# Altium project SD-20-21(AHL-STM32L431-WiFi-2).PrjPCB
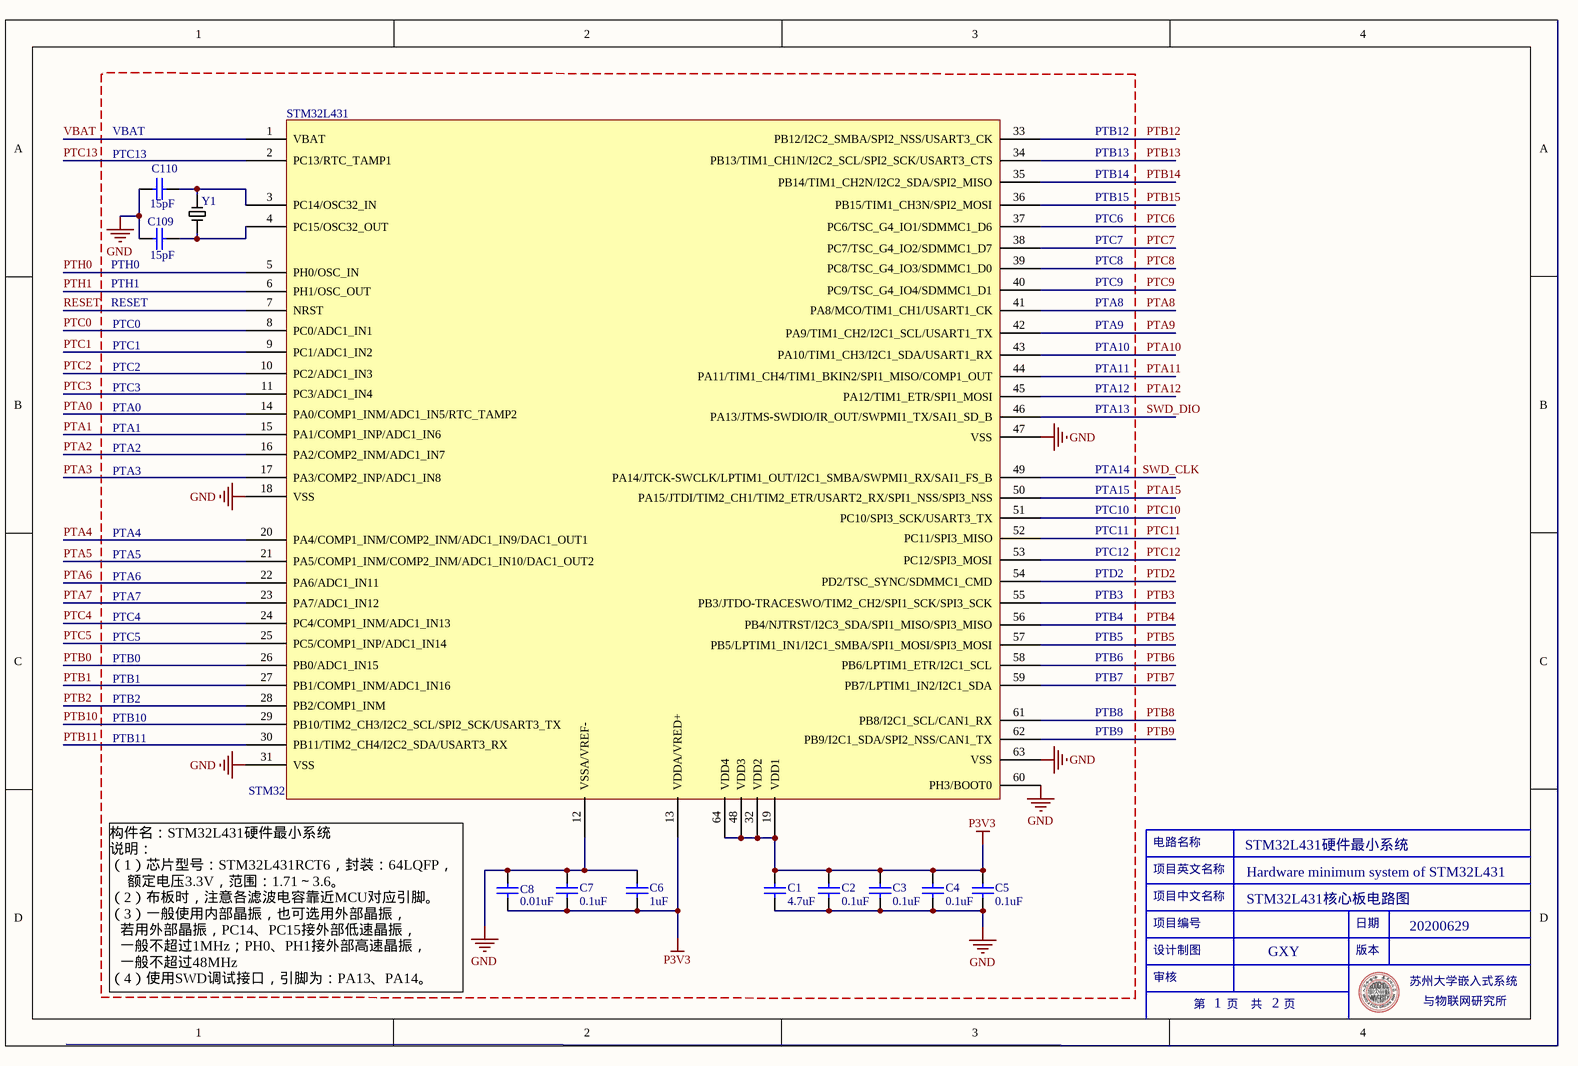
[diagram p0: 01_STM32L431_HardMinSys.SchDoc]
4 sheets, 60 parts. Net scope: global (net labels, ports and power ports of the same name join across sheets).
Board file: SD-20-21(AHL-STM32L431-WiFi-3).PcbDoc
Sheets:
  01_STM32L431_HardMinSys.SchDoc
  02_interface.SchDoc
  03_Wi-Fi-ESP8266.SchDoc
  Tsensor.SchDoc

## Sheet 01_STM32L431_HardMinSys.SchDoc
size A4; PageSetup: Record=PageOptions¦CenterHorizontal=True¦CenterVertical=True¦PrintScale=0.97¦XCorrection=1.00¦YCorrection=1.00¦PrintKind=1¦BorderSize=5000000¦LeftOffset=0¦BottomOffset=0¦Orientation=2¦PaperLength=1000¦PaperWidth=1000¦Scale=100¦PaperSource=15¦PrintQuality=1200¦MediaType=1¦DitherType=10¦PaperKind=A4¦PrintScaleMode=1

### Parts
C1  value 4.7uF  [0402]  (hidden comment: Cap)
C2  value 0.1uF  [0402]  (hidden comment: Cap)
C3  value 0.1uF  [0402]  (hidden comment: Cap)
C4  value 0.1uF  [0402]  (hidden comment: Cap)
C5  value 0.1uF  [0402]  (hidden comment: Cap)
C6  value 1uF  [0402]  (hidden comment: Cap)
C7  value 0.1uF  [0402]  (hidden comment: Cap)
C8  value 0.01uF  [0402]  (hidden comment: Cap)
C109  value 15pF  [0402]  (hidden comment: Cap)
C110  value 15pF  [0402]  (hidden comment: Cap)
STM32L431  STM32  [LQFP64]
Y1  resonnator  [osc]  (value not drawn)

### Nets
GND: C1.1 C2.1 C3.1 C4.1 C5.1 C6.1 C7.1 C8.1 C109.1 C110.1 STM32L431.12(VSSA/VREF-) STM32L431.18(VSS) STM32L431.31(VSS) STM32L431.47(VSS) STM32L431.60(PH3/BOOT0) STM32L431.63(VSS)
P3V3: C1.2 C2.2 C3.2 C4.2 C5.2 C6.2 C7.2 C8.2 STM32L431.13(VDDA/VRED+) STM32L431.19(VDD1) STM32L431.32(VDD2) STM32L431.48(VDD3) STM32L431.64(VDD4)
PTA0: STM32L431.14(PA0/COMP1_INM/ADC1_IN5/RTC_TAMP2)
PTA1: STM32L431.15(PA1/COMP1_INP/ADC1_IN6)
PTA2: STM32L431.16(PA2/COMP2_INM/ADC1_IN7)
PTA3: STM32L431.17(PA3/COMP2_INP/ADC1_IN8)
PTA4: STM32L431.20(PA4/COMP1_INM/COMP2_INM/ADC1_IN9/DAC1_OUT1)
PTA5: STM32L431.21(PA5/COMP1_INM/COMP2_INM/ADC1_IN10/DAC1_OUT2)
PTA6: STM32L431.22(PA6/ADC1_IN11)
PTA7: STM32L431.23(PA7/ADC1_IN12)
PTA8: STM32L431.41(PA8/MCO/TIM1_CH1/USART1_CK)
PTA9: STM32L431.42(PA9/TIM1_CH2/I2C1_SCL/USART1_TX)
PTA10: STM32L431.43(PA10/TIM1_CH3/I2C1_SDA/USART1_RX)
PTA11: STM32L431.44(PA11/TIM1_CH4/TIM1_BKIN2/SPI1_MISO/COMP1_OUT)
PTA12: STM32L431.45(PA12/TIM1_ETR/SPI1_MOSI)
PTA15: STM32L431.50(PA15/JTDI/TIM2_CH1/TIM2_ETR/USART2_RX/SPI1_NSS/SPI3_NSS)
PTB0: STM32L431.26(PB0/ADC1_IN15)
PTB1: STM32L431.27(PB1/COMP1_INM/ADC1_IN16)
PTB2: STM32L431.28(PB2/COMP1_INM)
PTB3: STM32L431.55(PB3/JTDO-TRACESWO/TIM2_CH2/SPI1_SCK/SPI3_SCK)
PTB4: STM32L431.56(PB4/NJTRST/I2C3_SDA/SPI1_MISO/SPI3_MISO)
PTB5: STM32L431.57(PB5/LPTIM1_IN1/I2C1_SMBA/SPI1_MOSI/SPI3_MOSI)
PTB6: STM32L431.58(PB6/LPTIM1_ETR/I2C1_SCL)
PTB7: STM32L431.59(PB7/LPTIM1_IN2/I2C1_SDA)
PTB8: STM32L431.61(PB8/I2C1_SCL/CAN1_RX)
PTB9: STM32L431.62(PB9/I2C1_SDA/SPI2_NSS/CAN1_TX)
PTB10: STM32L431.29(PB10/TIM2_CH3/I2C2_SCL/SPI2_SCK/USART3_TX)
PTB11: STM32L431.30(PB11/TIM2_CH4/I2C2_SDA/USART3_RX)
PTB12: STM32L431.33(PB12/I2C2_SMBA/SPI2_NSS/USART3_CK)
PTB13: STM32L431.34(PB13/TIM1_CH1N/I2C2_SCL/SPI2_SCK/USART3_CTS)
PTB14: STM32L431.35(PB14/TIM1_CH2N/I2C2_SDA/SPI2_MISO)
PTB15: STM32L431.36(PB15/TIM1_CH3N/SPI2_MOSI)
PTC0: STM32L431.8(PC0/ADC1_IN1)
PTC1: STM32L431.9(PC1/ADC1_IN2)
PTC2: STM32L431.10(PC2/ADC1_IN3)
PTC3: STM32L431.11(PC3/ADC1_IN4)
PTC4: STM32L431.24(PC4/COMP1_INM/ADC1_IN13)
PTC5: STM32L431.25(PC5/COMP1_INP/ADC1_IN14)
PTC6: STM32L431.37(PC6/TSC_G4_IO1/SDMMC1_D6)
PTC7: STM32L431.38(PC7/TSC_G4_IO2/SDMMC1_D7)
PTC8: STM32L431.39(PC8/TSC_G4_IO3/SDMMC1_D0)
PTC9: STM32L431.40(PC9/TSC_G4_IO4/SDMMC1_D1)
PTC10: STM32L431.51(PC10/SPI3_SCK/USART3_TX)
PTC11: STM32L431.52(PC11/SPI3_MISO)
PTC12: STM32L431.53(PC12/SPI3_MOSI)
PTC13: STM32L431.2(PC13/RTC_TAMP1)
PTD2: STM32L431.54(PD2/TSC_SYNC/SDMMC1_CMD)
PTH0: STM32L431.5(PH0/OSC_IN)
PTH1: STM32L431.6(PH1/OSC_OUT)
RESET: STM32L431.7(NRST)
SWD_CLK: STM32L431.49(PA14/JTCK-SWCLK/LPTIM1_OUT/I2C1_SMBA/SWPMI1_RX/SAI1_FS_B)
SWD_DIO: STM32L431.46(PA13/JTMS-SWDIO/IR_OUT/SWPMI1_TX/SAI1_SD_B)
VBAT: STM32L431.1(VBAT)
NetC109_2: C109.2 STM32L431.4(PC15/OSC32_OUT) Y1.2
NetC110_2: C110.2 STM32L431.3(PC14/OSC32_IN) Y1.1

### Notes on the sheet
- (near C110) PTC13
- (near C110) VBAT
- PTB12
- PTB13
- PTB14
- PTB15
- PTC6
- PTC7
- PTC8
- RESET
- (near C109) PTH1
- (near C109) PTH0
- PTC0
- PTC9
- PTA8
- PTA9
- PTC1
- PTC2
- PTC3
- PTA10
- PTA11
- PTA12
- PTA0
- PTA1
- PTA2
- PTA13
- PTA3
- PTC10
- PTC11
- PTA14
- PTA15
- PTA4
- PTA5
- PTA6
- PTA7
- PTC12
- PTB3
- PTD2
- PTC4
- PTC5
- PTB0
- PTB4
- PTB5
- PTB6
- PTB1
- PTB2
- PTB10
- PTB7
- PTB8
- PTB9
- PTB11
- STM32L431硬件最小系统
- STM32L431核心板电路图
- Hardware minimum system of STM32L431
- 20200629
- (near STM32L431) 构件名：STM32L431硬件最小系统
  说明：
  （1）芯片型号：STM32L431RCT6，封装：64LQFP，
  额定电压3.3V，范围：1.71～3.6。
  （2）布板时，注意各滤波电容靠近MCU对应引脚。
  （3）一般使用内部晶振，也可选用外部晶振，
  若用外部晶振，PC14、PC15接外部低速晶振，
  一般不超过1MHz；PH0、PH1接外部高速晶振，
  一般不超过48MHz
  （4）使用SWD调试接口，引脚为：PA13、PA14。
- GXY
- 1
- 2

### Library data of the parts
C1-C8 C109 C110 = Cap: Capacitor

## Sheet 02_interface.SchDoc
size A4; PageSetup: Record=PageOptions¦CenterHorizontal=True¦CenterVertical=True¦PrintScale=1.00¦XCorrection=1.00¦YCorrection=1.00¦PrintKind=1¦BorderSize=5000000¦LeftOffset=0¦BottomOffset=0¦Orientation=2¦PaperLength=1000¦PaperWidth=1000¦Scale=100¦PaperSource=15¦PrintQuality=1200¦MediaType=1¦DitherType=10¦PaperKind=A4¦PrintScaleMode=1
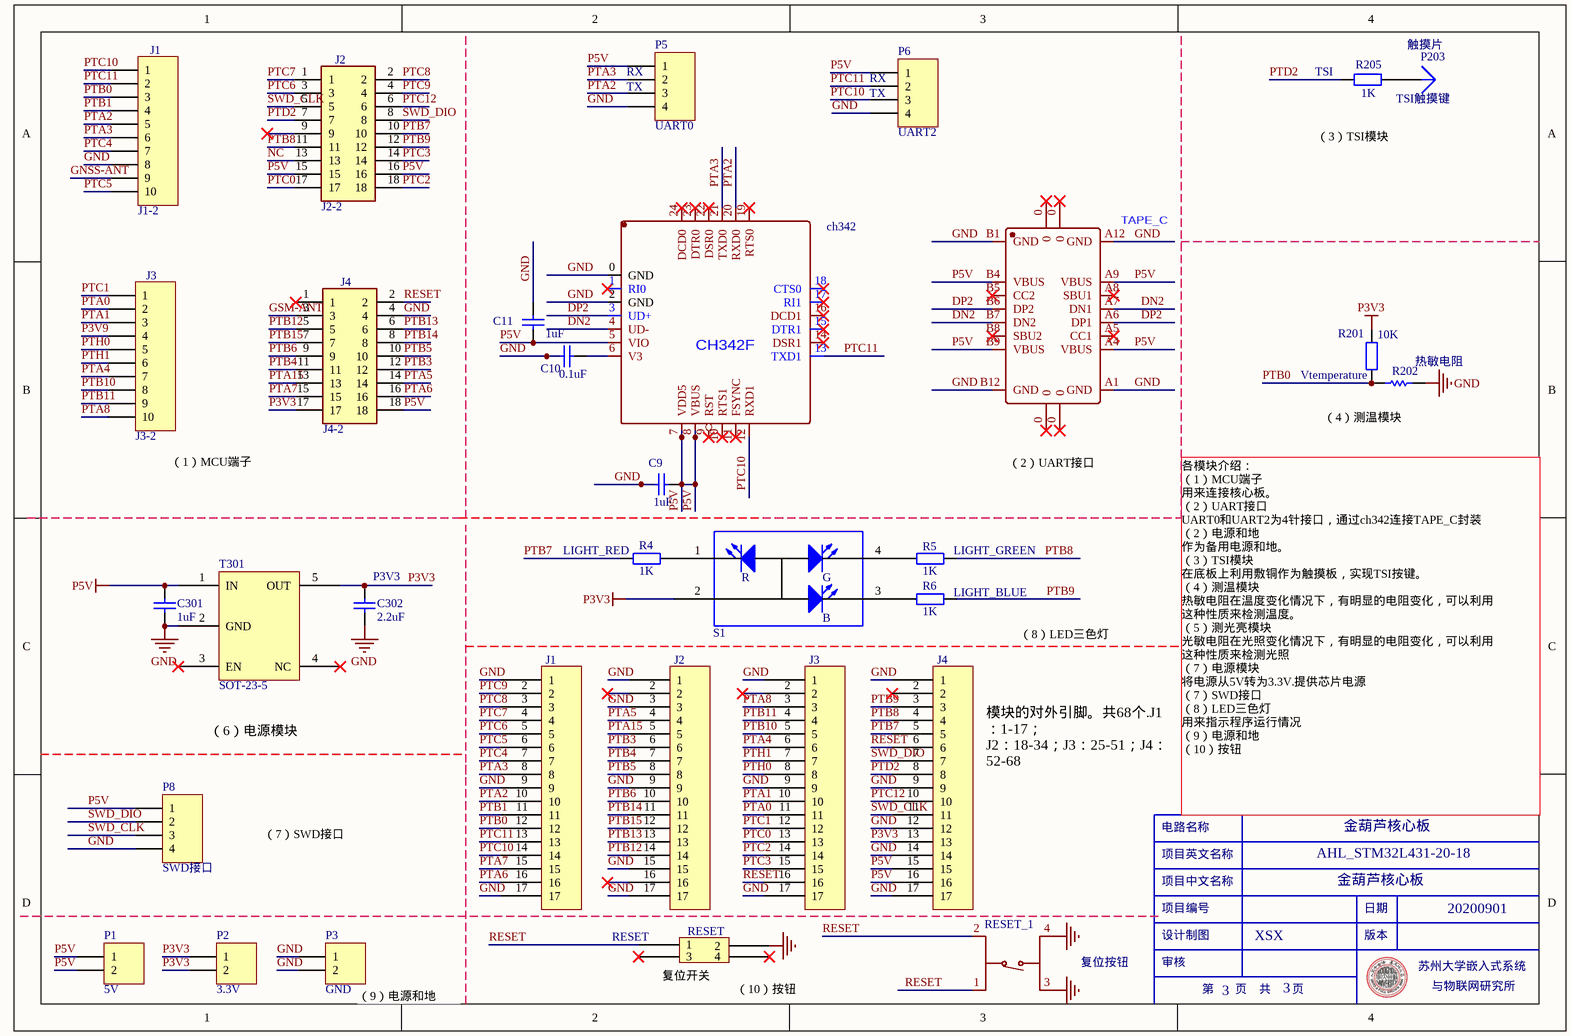
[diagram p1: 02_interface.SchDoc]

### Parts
(Parts that share a designator on the sheet are numbered #1, #2 ... from top to bottom, then left to right.)
C9  value 1uF  [0603]  (hidden comment: Cap)
C10  value 0.1uF  [0603]  (hidden comment: Cap)
C11  value 1uF  [0603]  (hidden comment: Cap)
C301  value 1uF  [0402]  (hidden comment: 0402)
C302  value 2.2uF  [0402]  (hidden comment: 0402)
ch342  ch342  [ch342]  (value not drawn)
J1#1  J1-2  [HDR1X10]
J1#2  HEADERX17(new)  [HEADERX17(new)]  (value not drawn)
J2#1  J2-2  [IDC2X9]
J2#2  HEADERX17(new)  [HEADERX17(new)]  (value not drawn)
J3#1  J3-2  [HDR1X10]
J3#2  HEADERX17(new)  [HEADERX17(new)]  (value not drawn)
J4#1  J4-2  [IDC2X9]
J4#2  HEADERX17(new)  [HEADERX17(new)]  (value not drawn)
P1  5V  [HDR1X2]
P2  3.3V  [HDR1X2]
P3  GND  [HDR1X2]
P5  UART0  [HDR1X4]
P6  UART2  [HDR1X4]
P8  SWD接口  [HDR1X4]
P203  TSI触摸键  [TSI]
R4  value 1K  [0603]  (hidden comment: Res2)
R5  value 1K  [0603]  (hidden comment: Res2)
R6  value 1K  [0603]  (hidden comment: Res2)
R201  value 10K  [0603]  (hidden comment: Res2)
R202  热敏电阻  [0603]
R205  value 1K  [0603]  (hidden comment: Res2)
RESET  RESET  [RESET_KEY]  (value not drawn)
RESET_1  复位按钮  [复位按钮]
S1  Single-Pole, Single-Throw Switch  [LED3]  (value not drawn)
T301  SOT-23-5  [SOT-23-5]
TAPE_C  TYPE-C-31-M-12  [TYPE_C]  (value not drawn)

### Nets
GND: C9.2 C10.1 C11.2 C301.1 C302.1 ch342.0(GND) ch342.2(GND) J1#1.8 J1#2.1 J1#2.9 J1#2.17 J2#2.1 J2#2.3 J2#2.9 J2#2.15 J2#2.17 J3#2.1 J3#2.9 J3#2.17 J4#1.4 J4#2.1 J4#2.9 J4#2.12 J4#2.14 J4#2.17 P3.1 P3.2 P5.4 P6.4 P8.4 R202.1 RESET.2 RESET_1.3(C) RESET_1.4(D) T301.2(GND) TAPE_C.A1(GND) TAPE_C.A12(GND) TAPE_C.B1(GND) TAPE_C.B12(GND)
P3V3: C302.2 J4#1.17 J4#2.13 P2.1 P2.2 R201.2 S1.2 T301.5(OUT)
P5V: C9.1 C11.1 C301.2 ch342.5(VIO) ch342.7(VDD5) ch342.8(VBUS) J2#1.15 J2#1.16 J4#1.18 J4#2.15 J4#2.16 P1.1 P1.2 P5.1 P6.1 P8.1 T301.1(IN) TAPE_C.A4(VBUS) TAPE_C.A9(VBUS) TAPE_C.B4(VBUS) TAPE_C.B9(VBUS)
DN2: ch342.4(UD-) TAPE_C.A7(DN1) TAPE_C.B7(DN2)
DP2: ch342.3(UD+) TAPE_C.A6(DP1) TAPE_C.B6(DP2)
GNSS-ANT: J1#1.9
GSM-ANT: J4#1.3
NC: J2#1.13
P3V9: J3#1.4
PTA0: J3#1.2 J3#2.11
PTA1: J3#1.3 J3#2.10
PTA2: ch342.20(RXD0) J1#1.5 J1#2.10 P5.3
PTA3: ch342.21(TXD0) J1#1.6 J1#2.8 P5.2
PTA4: J3#1.7 J3#2.6
PTA5: J2#2.4 J4#1.14
PTA6: J1#2.16 J4#1.16
PTA7: J1#2.15 J4#1.15
PTA8: J3#1.10 J3#2.3
PTA15: J2#2.5 J4#1.13
PTB0: J1#1.3 J1#2.12 R201.1 R202.2
PTB1: J1#1.4 J1#2.11
PTB3: J2#2.6 J4#1.12
PTB4: J2#2.7 J4#1.11
PTB5: J2#2.8 J4#1.10
PTB6: J2#2.10 J4#1.9
PTB7: J2#1.10 J4#2.5 R4.1
PTB8: J2#1.11 J4#2.4 R5.2
PTB9: J2#1.12 J4#2.3 R6.2
PTB10: J3#1.8 J3#2.5
PTB11: J3#1.9 J3#2.4
PTB12: J2#2.14 J4#1.5
PTB13: J2#2.13 J4#1.6
PTB14: J2#2.11 J4#1.8
PTB15: J2#2.12 J4#1.7
PTC0: J2#1.17 J3#2.13
PTC1: J3#1.1 J3#2.12
PTC2: J2#1.18 J3#2.14
PTC3: J2#1.14 J3#2.15
PTC4: J1#1.7 J1#2.7
PTC5: J1#1.10 J1#2.6
PTC6: J1#2.5 J2#1.3
PTC7: J1#2.4 J2#1.1
PTC8: J1#2.3 J2#1.2
PTC9: J1#2.2 J2#1.4
PTC10: ch342.12(RXD1) J1#1.1 J1#2.14 P6.3
PTC11: ch342.13(TXD1) J1#1.2 J1#2.13 P6.2
PTC12: J2#1.6 J4#2.10
PTD2: J2#1.7 J4#2.8 R205.1
PTH0: J3#1.5 J3#2.8
PTH1: J3#1.6 J3#2.7
RESET: J3#2.16 J4#1.2 J4#2.6 RESET.1 RESET_1.1(A) RESET_1.2(B)
SWD_CLK: J2#1.5 J4#2.11 P8.3
SWD_DIO: J2#1.8 J4#2.7 P8.2
NetC10_2: C10.2 ch342.6(V3)
NetP203_1: P203.1 R205.2
NetR4_2: R4.2 S1.1
NetR5_1: R5.1 S1.4
NetR6_1: R6.1 S1.3

Not connected (* = marked no-connect by the designer): ch342 1(RI0)* 9(RST)* 10(RTS1)* 11(FSYNC)* 14(DSR1)* 15(DTR1)* 16(DCD1)* 17(RI1)* 18(CTS0)* 19(RTS0)* 22(DSR0)* 23(DTR0)* 24(DCD0)*; J2#1 9*; J2#2 2* 16*; J3#2 2*; J4#1 1*; J4#2 2*; RESET 3* 4*; T301 3(EN)* 4(NC)*; TAPE_C 0* A5(CC1)* A8(SBU1)* B5(CC2)* B8(SBU2)*

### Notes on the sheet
- (near P5) TX
- (near P5) RX
- (near P6) TX
- (near P6) RX
- (near R205) TSI
- 触摸片
- （3）TSI模块
- (near R201) Vtemperature
- （4）测温模块
- （1）MCU端子
- (near TAPE_C) （2）UART接口
- (near C302) P3V3
- (near R4) LIGHT_RED
- (near R5) LIGHT_GREEN
- (near R6) LIGHT_BLUE
- （8）LED三色灯
- （6）电源模块
- (near J4#2) 模块的对外引脚。共68个.J1：1-17；
  J2：18-34；J3：25-51；J4：52-68
- （7）SWD接口
- 各模块介绍：
  （1）MCU端子
  用来连接核心板。
  （2）UART接口
  UART0和UART2为4针接口，通过ch342连接TAPE_C封装
  （2）电源和地
  作为备用电源和地。
  （3）TSI模块
  在底板上利用敷铜作为触摸板，实现TSI按键。
  （4）测温模块
  热敏电阻在温度变化情况下，有明显的电阻变化，可以利用
  这种性质来检测温度。
  （5）测光亮模块
  光敏电阻在光照变化情况下，有明显的电阻变化，可以利用
  这种性质来检测光照
  （7）电源模块
  将电源从5V转为3.3V.提供芯片电源
  （7）SWD接口
  （8）LED三色灯
  用来指示程序运行情况
  （9）电源和地
  （10）按钮
- 金葫芦核心板
- AHL_STM32L431-20-18
- 20200901
- RESET
- (near RESET) 复位开关
- XSX
- (near P3) （9）电源和地
- (near RESET) （10）按钮
- 3

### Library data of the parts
C9-C11 = Cap: Capacitor
C301 C302 = Cap: Capacitor; Manufacturer: Generic Components; Class: Passive
J1#1 J3#1 = Header 10: Header, 10-Pin
J2#1 J4#1 = CON2X9
P1-P3 = Header 2: Header, 2-Pin
P5 P6 P8 = Header 4: Header, 4-Pin
P203 = Plug
R4-R6 R201 R205 = Res2: Resistor
R202 = Res1: Resistor; Value: 1K
S1 = LED_3
T301 = SOT-23-5: TPS70933

## Sheet 03_Wi-Fi-ESP8266.SchDoc
size A4; PageSetup: Record=PageOptions¦CenterHorizontal=True¦CenterVertical=True¦PrintScale=1.00¦XCorrection=1.00¦YCorrection=1.00¦PrintKind=1¦BorderSize=5000000¦LeftOffset=0¦BottomOffset=0¦Orientation=2¦PaperLength=1000¦PaperWidth=1000¦Scale=100¦PaperSource=15¦PrintQuality=1200¦MediaType=1¦DitherType=10¦PaperKind=A4¦PrintScaleMode=1
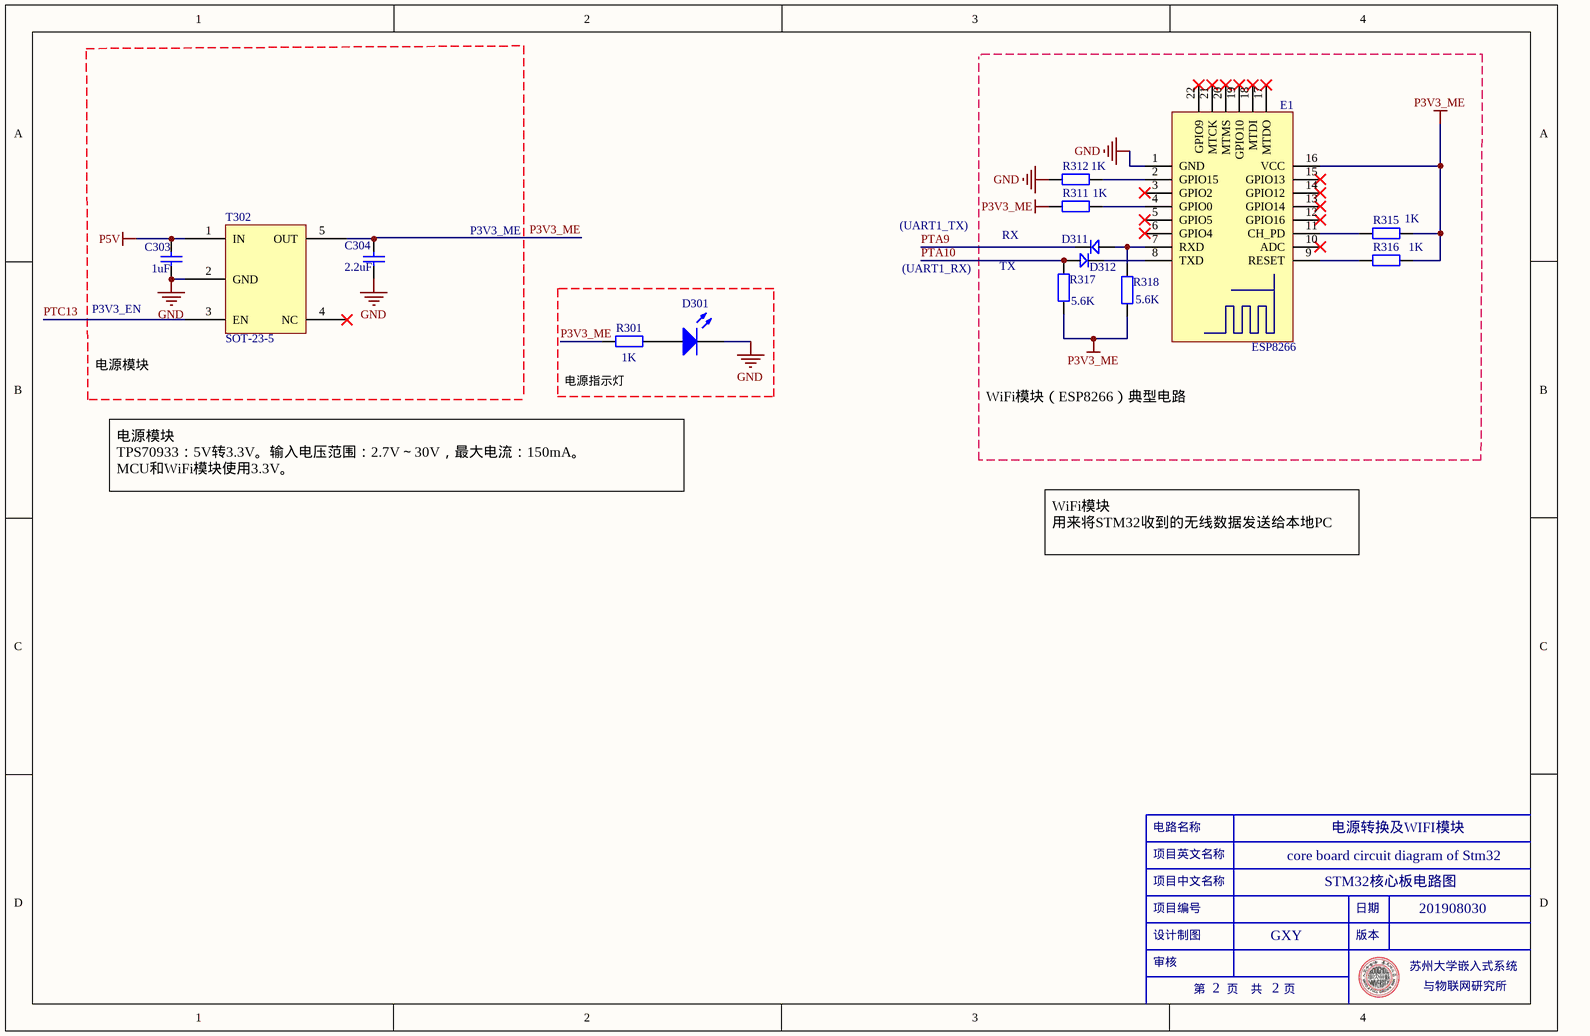
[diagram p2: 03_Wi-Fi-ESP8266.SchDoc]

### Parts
C303  value 1uF  [0402]  (hidden comment: 0402)
C304  value 2.2uF  [0402]  (hidden comment: 0402)
D301  LED3  [0603+]  (value not drawn)
D311  MBR0520  [SOD-123]  (value not drawn)
D312  MBR0520  [SOD-123]  (value not drawn)
E1  ESP8266  [ESP8266]
R301  value 1K  [0402]  (hidden comment: Res2)
R311  value 1K  [0603]  (hidden comment: Res2)
R312  value 1K  [0603]  (hidden comment: Res2)
R315  value 1K  [0603]  (hidden comment: *)
R316  value 1K  [0603]  (hidden comment: *)
R317  value 5.6K  [0603]  (hidden comment: Res2)
R318  value 5.6K  [0603]  (hidden comment: Res2)
T302  SOT-23-5  [SOT-23-5]

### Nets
GND: C303.1 C304.1 D301.2(K) E1.1(GND) R312.1 T302.2(GND)
P3V3_ME: C304.2 E1.16(VCC) R301.1 R311.1 R315.2 R316.2 R317.2 R318.2 T302.5(OUT)
P5V: C303.2 T302.1(IN)
PTA9: D311.2
PTA10: D312.1 R317.1
PTC13: T302.3(EN)
NetD301_1: D301.1(A) R301.2
NetD311_1: D311.1 E1.7(RXD) R318.1
NetD312_2: D312.2 E1.8(TXD)
NetE1_2: E1.2(GPIO15) R312.2
NetE1_4: E1.4(GPIO0) R311.2
NetE1_9: E1.9(RESET) R316.1
NetE1_11: E1.11(CH_PD) R315.1

Not connected (* = marked no-connect by the designer): E1 3(GPIO2)* 5(GPIO5)* 6(GPIO4)* 10(ADC)* 12(GPIO16)* 13(GPIO14)* 14(GPIO12)* 15(GPIO13)* 17(MTDO)* 18(MTDI)* 19(GPIO10)* 20(MTMS)* 21(MTCK)* 22(GPIO9)*; T302 4(NC)*

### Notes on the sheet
- P3V3_ME
- (UART1_TX)
- RX
- (near C303) P3V3_EN
- (UART1_RX)
- TX
- (near T302) 电源模块
- 电源指示灯
- WiFi模块（ESP8266）典型电路
- 电源模块
  TPS70933：5V转3.3V。输入电压范围：2.7V～30V，最大电流：150mA。
  MCU和WiFi模块使用3.3V。
- WiFi模块
  用来将STM32收到的无线数据发送给本地PC
- 电源转换及WIFI模块
- core board circuit diagram of Stm32
- STM32核心板电路图
- 201908030
- GXY
- 2

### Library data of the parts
C303 C304 = Cap: as C301 on sheet 02_interface
D301 = LED3: Typical BLUE SiC LED
R301 R311 R312 R315-R318 = Res2: Resistor
T302 = SOT-23-5: TPS70933

## Sheet Tsensor.SchDoc
size A4
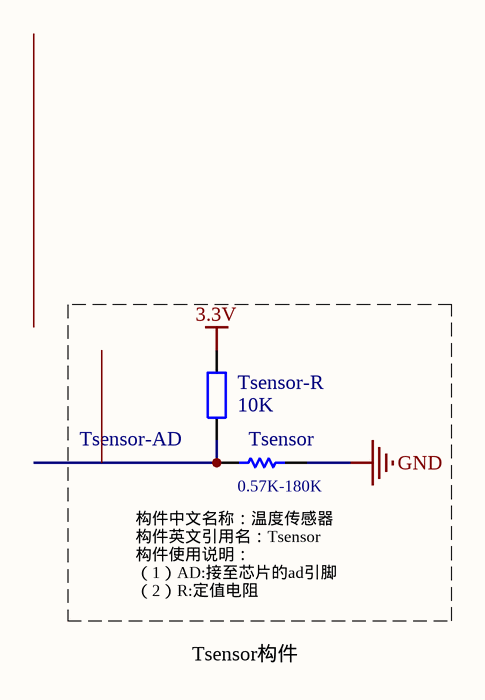
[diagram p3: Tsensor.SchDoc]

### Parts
Tsensor  0.57K-180K  [0603]
Tsensor-R  value 10K  [0603]  (hidden comment: Res2)

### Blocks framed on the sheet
Tsensor-AD: Tsensor Tsensor-R

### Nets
3.3V: Tsensor-R.2
GND: Tsensor.1
NetTsensor_2: Tsensor.2 Tsensor-R.1

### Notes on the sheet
- (near Tsensor) 构件中文名称：温度传感器
  构件英文引用名：Tsensor
  构件使用说明：
  （1）AD:接至芯片的ad引脚
  （2）R:定值电阻
- Tsensor构件

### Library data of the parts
Tsensor = Res1: Resistor; Value: 1K
Tsensor-R = Res2: Resistor

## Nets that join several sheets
GND: 01_STM32L431_HardMinSys (16 pins), 02_interface (39 pins), 03_Wi-Fi-ESP8266 (6 pins), Tsensor (Tsensor.1)
P3V3: 01_STM32L431_HardMinSys (13 pins), 02_interface (8 pins)
P5V: 02_interface (21 pins), 03_Wi-Fi-ESP8266 (C303.2 T302.1)
PTA0: 01_STM32L431_HardMinSys (STM32L431.14), 02_interface (J3#1.2 J3#2.11)
PTA1: 01_STM32L431_HardMinSys (STM32L431.15), 02_interface (J3#1.3 J3#2.10)
PTA2: 01_STM32L431_HardMinSys (STM32L431.16), 02_interface (ch342.20 J1#1.5 J1#2.10 P5.3)
PTA3: 01_STM32L431_HardMinSys (STM32L431.17), 02_interface (ch342.21 J1#1.6 J1#2.8 P5.2)
PTA4: 01_STM32L431_HardMinSys (STM32L431.20), 02_interface (J3#1.7 J3#2.6)
PTA5: 01_STM32L431_HardMinSys (STM32L431.21), 02_interface (J2#2.4 J4#1.14)
PTA6: 01_STM32L431_HardMinSys (STM32L431.22), 02_interface (J1#2.16 J4#1.16)
PTA7: 01_STM32L431_HardMinSys (STM32L431.23), 02_interface (J1#2.15 J4#1.15)
PTA8: 01_STM32L431_HardMinSys (STM32L431.41), 02_interface (J3#1.10 J3#2.3)
PTA9: 01_STM32L431_HardMinSys (STM32L431.42), 03_Wi-Fi-ESP8266 (D311.2)
PTA10: 01_STM32L431_HardMinSys (STM32L431.43), 03_Wi-Fi-ESP8266 (D312.1 R317.1)
PTA15: 01_STM32L431_HardMinSys (STM32L431.50), 02_interface (J2#2.5 J4#1.13)
PTB0: 01_STM32L431_HardMinSys (STM32L431.26), 02_interface (J1#1.3 J1#2.12 R201.1 R202.2)
PTB1: 01_STM32L431_HardMinSys (STM32L431.27), 02_interface (J1#1.4 J1#2.11)
PTB3: 01_STM32L431_HardMinSys (STM32L431.55), 02_interface (J2#2.6 J4#1.12)
PTB4: 01_STM32L431_HardMinSys (STM32L431.56), 02_interface (J2#2.7 J4#1.11)
PTB5: 01_STM32L431_HardMinSys (STM32L431.57), 02_interface (J2#2.8 J4#1.10)
PTB6: 01_STM32L431_HardMinSys (STM32L431.58), 02_interface (J2#2.10 J4#1.9)
PTB7: 01_STM32L431_HardMinSys (STM32L431.59), 02_interface (J2#1.10 J4#2.5 R4.1)
PTB8: 01_STM32L431_HardMinSys (STM32L431.61), 02_interface (J2#1.11 J4#2.4 R5.2)
PTB9: 01_STM32L431_HardMinSys (STM32L431.62), 02_interface (J2#1.12 J4#2.3 R6.2)
PTB10: 01_STM32L431_HardMinSys (STM32L431.29), 02_interface (J3#1.8 J3#2.5)
PTB11: 01_STM32L431_HardMinSys (STM32L431.30), 02_interface (J3#1.9 J3#2.4)
PTB12: 01_STM32L431_HardMinSys (STM32L431.33), 02_interface (J2#2.14 J4#1.5)
PTB13: 01_STM32L431_HardMinSys (STM32L431.34), 02_interface (J2#2.13 J4#1.6)
PTB14: 01_STM32L431_HardMinSys (STM32L431.35), 02_interface (J2#2.11 J4#1.8)
PTB15: 01_STM32L431_HardMinSys (STM32L431.36), 02_interface (J2#2.12 J4#1.7)
PTC0: 01_STM32L431_HardMinSys (STM32L431.8), 02_interface (J2#1.17 J3#2.13)
PTC1: 01_STM32L431_HardMinSys (STM32L431.9), 02_interface (J3#1.1 J3#2.12)
PTC2: 01_STM32L431_HardMinSys (STM32L431.10), 02_interface (J2#1.18 J3#2.14)
PTC3: 01_STM32L431_HardMinSys (STM32L431.11), 02_interface (J2#1.14 J3#2.15)
PTC4: 01_STM32L431_HardMinSys (STM32L431.24), 02_interface (J1#1.7 J1#2.7)
PTC5: 01_STM32L431_HardMinSys (STM32L431.25), 02_interface (J1#1.10 J1#2.6)
PTC6: 01_STM32L431_HardMinSys (STM32L431.37), 02_interface (J1#2.5 J2#1.3)
PTC7: 01_STM32L431_HardMinSys (STM32L431.38), 02_interface (J1#2.4 J2#1.1)
PTC8: 01_STM32L431_HardMinSys (STM32L431.39), 02_interface (J1#2.3 J2#1.2)
PTC9: 01_STM32L431_HardMinSys (STM32L431.40), 02_interface (J1#2.2 J2#1.4)
PTC10: 01_STM32L431_HardMinSys (STM32L431.51), 02_interface (ch342.12 J1#1.1 J1#2.14 P6.3)
PTC11: 01_STM32L431_HardMinSys (STM32L431.52), 02_interface (ch342.13 J1#1.2 J1#2.13 P6.2)
PTC12: 01_STM32L431_HardMinSys (STM32L431.53), 02_interface (J2#1.6 J4#2.10)
PTC13: 01_STM32L431_HardMinSys (STM32L431.2), 03_Wi-Fi-ESP8266 (T302.3)
PTD2: 01_STM32L431_HardMinSys (STM32L431.54), 02_interface (J2#1.7 J4#2.8 R205.1)
PTH0: 01_STM32L431_HardMinSys (STM32L431.5), 02_interface (J3#1.5 J3#2.8)
PTH1: 01_STM32L431_HardMinSys (STM32L431.6), 02_interface (J3#1.6 J3#2.7)
RESET: 01_STM32L431_HardMinSys (STM32L431.7), 02_interface (6 pins)
SWD_CLK: 01_STM32L431_HardMinSys (STM32L431.49), 02_interface (J2#1.5 J4#2.11 P8.3)
SWD_DIO: 01_STM32L431_HardMinSys (STM32L431.46), 02_interface (J2#1.8 J4#2.7 P8.2)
